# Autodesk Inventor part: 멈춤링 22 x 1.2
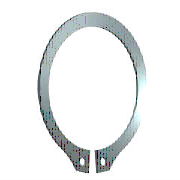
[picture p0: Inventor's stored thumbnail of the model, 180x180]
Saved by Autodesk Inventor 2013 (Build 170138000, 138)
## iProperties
IsCustomPart: 0
Company: 한국ATC센터
Created: 2014-07
Part Number: 멈춤링 22 x 1.2
Material: Steel, Mild
Description: 리테이닝 링(C형)
Document SubType Name: Modeling
Standard: KS B 1336
Designer: KYOUNG IL JANG
Standards Organization: KS
Language: ko-KR
Size Designation: 22 x 1.2
Categories: <MemberInstance><Categories><Category DisplayName="샤프트 부품" InternalName="7f7aeb1f-a693-4053-b835-cee3144e0d98" Mnemonic="SHFT"><Category DisplayName="써클립" Inter
Density: 7.86 g/cm^3
Mass: 1.82859 g
Surface Area: 5.91219 cm^2
Volume: 0.232645 cm^3
Author: KYOUNG IL JANG
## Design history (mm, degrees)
sketch "스케치1"
  geometry: L1 (-6, 0)-(6, 0) reference; L2 (0, 20.189)-(0, -80.536) reference; L3 (-48.09, 0)-(48.09, 0) reference; L4 (-0.5, -21.488)-(-0.5, -25.588); L5 (-0.5, -6.54)-(-0.5, -13.29); L6 (-2.795, 2.7)-(3.672, 2.7); L7 (0.5, -6.54)-(0.5, -13.29); L8 (0.5, -21.488)-(0.5, -25.588); C1 r 1 at (-2, -23.437); C2 r 1 at (2, -23.437); A1 r 10.5 centre (0, -11) between (0.5, -21.488) and (-0.5, -21.488); A2 r 13.025 centre (0, -10.325) between (5.149, -22.289) and (-5.149, -22.289); A3 r 14.597 centre (0, -11) between (-2.318, -25.411) and (-0.5, -25.588); A4 r 2 centre (-2, -23.437) between (-3.97, -23.781) and (-2.318, -25.411); A5 r 2 centre (-5.94, -24.126) between (-3.97, -23.781) and (-5.149, -22.289); A6 r 2 centre (5.94, -24.126) between (5.149, -22.289) and (3.97, -23.781); A7 r 2 centre (2, -23.437) between (2.318, -25.411) and (3.97, -23.781); A8 r 14.597 centre (0, -11) between (0.5, -25.588) and (2.318, -25.411)
  constraints: 16 point on circle, 12 end point, 10 centre point, 9 symmetric about line, 5 point on line, 4 tangent, 3 coincident, 2 horizontal, 1 perpendicular, 1 vertical, 5 other
  dimensions: "d0" = 21 diameter of A1 (= ND); "d1" = 4.1 distance of L4.end L4.start (= SRB2); "d6" = 0.5 distance between parallel lines of L2 L5 (= 0.25 x SD5); "d7" = 2.7 distance between parallel lines of L6 L3 (= SRB1); "d8" = 0.675 distance of A1.centre A2.centre (= 0.25 x SRB1); "d9" = 2 radius of A4 (= SD5); "d10" = 2 radius of A5 (= SD5); "d11" = 1.5 distance from line of L4 A4.centre (= 0.75 x SD5); "d12" = 2 diameter of C1 (= SD5); "d13" = 2 diameter of C2 (= SD5); "d14" = 11 distance from line of A1.centre L1 (= 0.5 x WD)
extrude "본체" new body sketch "스케치1" distance "d2" = 1.2 (= SD); taper "d3" = 0 deg
workaxis "Work Axis1"
workplane "Work Plane1"
body "Solid1"
other parameters: "WD" = 22 (= WDMIN) [user parameter; used in 1 equation term], "SD" = 1.2 [user parameter; used in 1 equation term], "SRB1" = 2.7 [user parameter; used in 2 equation terms], "ND" = 21 [user parameter; used in 1 equation term], "SRB2" = 4.1 [user parameter; used in 1 equation term], "SD5" = 2 [user parameter; used in 6 equation terms], "d15" = 0, "d16" = 0, "d17" = 0, "d41" = 0, "d42" = 0, "WDMIN" = 22 [user parameter; used in 1 equation term], "SD3" = 20.5 [user parameter], "WDMAX" = 24 [user parameter]
